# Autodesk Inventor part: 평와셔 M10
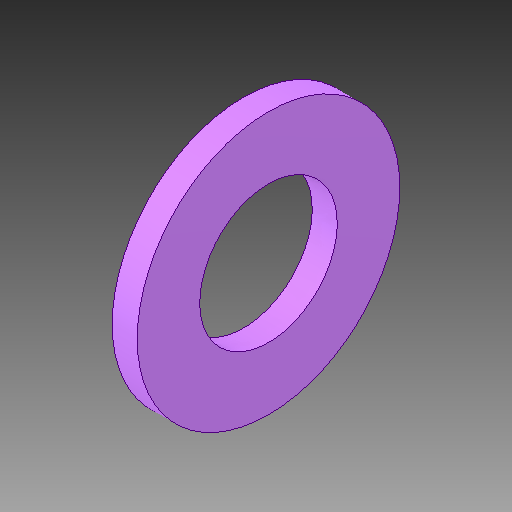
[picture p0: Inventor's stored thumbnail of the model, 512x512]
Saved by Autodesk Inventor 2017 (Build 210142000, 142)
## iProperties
Created: 2024-09
Part Number: 평와셔 M10
Material: 일반
Description: 평면 와셔
Document SubType Name: Modeling
Designer: MRC
Density: 1 g/cm^3
Appearance: 기본값
Author: jhkim
Sending System: Autodesk Inventor 2025
Preprocessor: ST-DEVELOPER v20
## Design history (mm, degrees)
feature "Solid1"
node "솔리드1"
